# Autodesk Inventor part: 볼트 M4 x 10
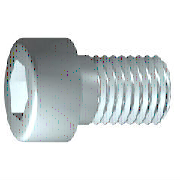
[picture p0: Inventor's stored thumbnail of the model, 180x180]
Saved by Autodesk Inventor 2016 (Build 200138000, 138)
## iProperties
IsCustomPart: 0
Created: 2012-02
Part Number: 볼트 M4 x 10
Material: 스테인리스강
Description: 6각 소켓 머리 캡 나사
Document SubType Name: Modeling
Standard: ISO 4762
Designer: mduedu
Standard Revision: Fourth edition 2004-03-01
Standards Organization: ISO
Language: ko-KR
Size Designation: M4 x 10
Categories: <MemberInstance><Categories><Category DisplayName="조임쇠" InternalName="e4da775c-781d-43d5-af7c-5136215cf5a6" Mnemonic="FSTN"><Category DisplayName="볼트" InternalN
Density: 8.08 g/cm^3
Appearance: 반광택
Author: mduedu
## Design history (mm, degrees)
sketch "스케치1"
  geometry: L1 (-1, 0)-(10, 0); L2 (10, 0)-(10, 2); L3 (10, 2)-(1.75, 2); L4 (1.75, 2)-(1.32, 2); L5 (1.32, 2)-(0, 2); L6 (0, 2)-(0, 3.5); L7 (0, 3.5)-(-4, 3.5); L8 (-4, 3.5)-(-4, 1.732); L9 (-4, 1.732)-(-2, 1.732); L10 (-2, 1.732)-(-1, 0); L11 (-6.8, 0)-(12.8, 0) reference; L12 (0, -0.7)-(0, 4.2) reference; L13 (1.75, 2)-(0, 2)
  constraints: 22 end point, 6 parallel, 2 collinear, 2 perpendicular, 1 horizontal, 1 point on line
  dimensions: "d1" = 8.25 distance from line of L3.end L2 (= GEL); "d2" = 0.42952 distance of L4.end L3.end (computed from GAL); "d3" = 4 distance between parallel lines of L8 L6 (= KOH); "d4" = 2 distance of L8.end L9.end (= INTI); "d5" = 60 deg angle of L10 L1; "d6" = 4 diameter of L3 L1 (= GD); "d7" = 4 diameter of L5 L1 (= BDM); "d8" = 3.4641 diameter of L9 L1 (= 1.1547 x SW); "d9" = 7 diameter of L7 L1 (= KOD); "d26" = 10 distance between parallel lines of L12 L2 (= NLG)
revolve "본체" sketch "스케치1" stored, may be unused: angle "d10" = 90 deg
sketch "스케치2"
  geometry: L1 (0, -4.9)-(0, 4.9) reference; L2 (-4.9, 0)-(4.9, 0) reference; L3 (1.732, 0)-(0.866, -1.5); L4 (0.866, -1.5)-(-0.866, -1.5); L5 (-0.866, -1.5)-(-1.732, 0); L6 (-1.732, 0)-(-0.866, 1.5); L7 (-0.866, 1.5)-(0.866, 1.5); L8 (0.866, 1.5)-(1.732, 0); 2 further points
  constraints: 12 end point, 1 coincident, 1 horizontal alignment, 1 point on line, 12 other
extrude "슬롯" join sketch "스케치2" stored distance "d11" = 10; taper "d12" = 0 deg
workplane "Work Plane1"
fillet "Fillet2" dims "d30" = 0.1 (= R)
body "Solid1"
fillet "모깎기1" dims "d17" = 0.4 (= RR)
feature "스레드" dims "d13" = 8.25 (= GEL), "d14" = 0
chamfer "모따기1" distance "d15" = 0.42941 (= -0.5 x SPD + 0.5 x GD); stored, may be unused: second distance "d16" = 0.42941 (= GUL), angle "d27" = 45 deg
other parameters: "GD" = 4 [user parameter; used in 2 equation terms], "NLG" = 10 [user parameter; used in 1 equation term], "GEL" = 8.25 [user parameter; used in 2 equation terms], "KOD" = 7 [user parameter; used in 1 equation term], "KOH" = 4 [user parameter; used in 1 equation term], "INTI" = 2 [user parameter; used in 1 equation term], "GAL" = 0.42941 (= 0.61345 x PTC) [user parameter; used in 1 equation term], "GUL" = 0.42941 (= 0.61345 x PTC) [user parameter; used in 1 equation term], "BDM" = 4 (= NND) [user parameter; used in 1 equation term], "SW" = 3 [user parameter; used in 2 equation terms], "RR" = 0.4 [user parameter; used in 1 equation term], "SPD" = 3.14117 (= NND - 1.2269 x PTC) [user parameter; used in 1 equation term], "d19" = 0, "d28" = 0, "d29" = 0, "R" = 0.1 [user parameter; used in 1 equation term], "TOA" = 30 deg [user parameter], "GD1" = 3.14117 (= THREADDIA - 1.2269 x PTC) [user parameter], "THREADDIA" = 4 [user parameter; used in 1 equation term], "FAWI" = 45 deg [user parameter], "TPU" = 14.28571 (computed from PTC) [user parameter], "PTC" = 0.7 [user parameter; used in 5 equation terms], "NND" = 4 [user parameter; used in 2 equation terms], "E0" = 3.465 (= 1.155 x SW) [user parameter]
